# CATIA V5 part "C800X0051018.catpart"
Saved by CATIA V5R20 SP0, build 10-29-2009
Part number: C800X0051018
Source: Unknown
Property "A": "30"
Property "ARTICLENO": "C800X0051018"
Property "B": "13"
Property "BOMINFO": "C800X0051018"
Property "C": "46"
Property "CA": "C800X0051018"
Property "D1": "38"
Property "DES": "ROTATING EYEBOLT WITH RING Ton 0,5 M10x18"
Property "E": "50"
Property "H": "105"
Property "L": "18"
Property "LINA": "C800X0051018"
Property "NB": "C800X0051018"
Property "NBSYN": "$CODE."
Property "NN": "C800X"
Property "NT": "Rotating eyebolt with ring"
Property "SIZE": "M10"
Property "SUPPLIER": "CF"
Property "SW": "30"
Property "WEIGHT": "480"
Property "WLL": "0.50"
Bounding box of the stored display mesh (mm): x -27.837 to 27.837, y -18 to 117.837, z -19 to 19
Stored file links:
  C:\Users\Utente\Desktop\3D files 800X\C800X0051018.catpart

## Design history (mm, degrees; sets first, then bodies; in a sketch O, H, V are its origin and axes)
Body1 "Geometry.1" (main body)
  Solid1 "C800X0051018.catpart": solid without history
